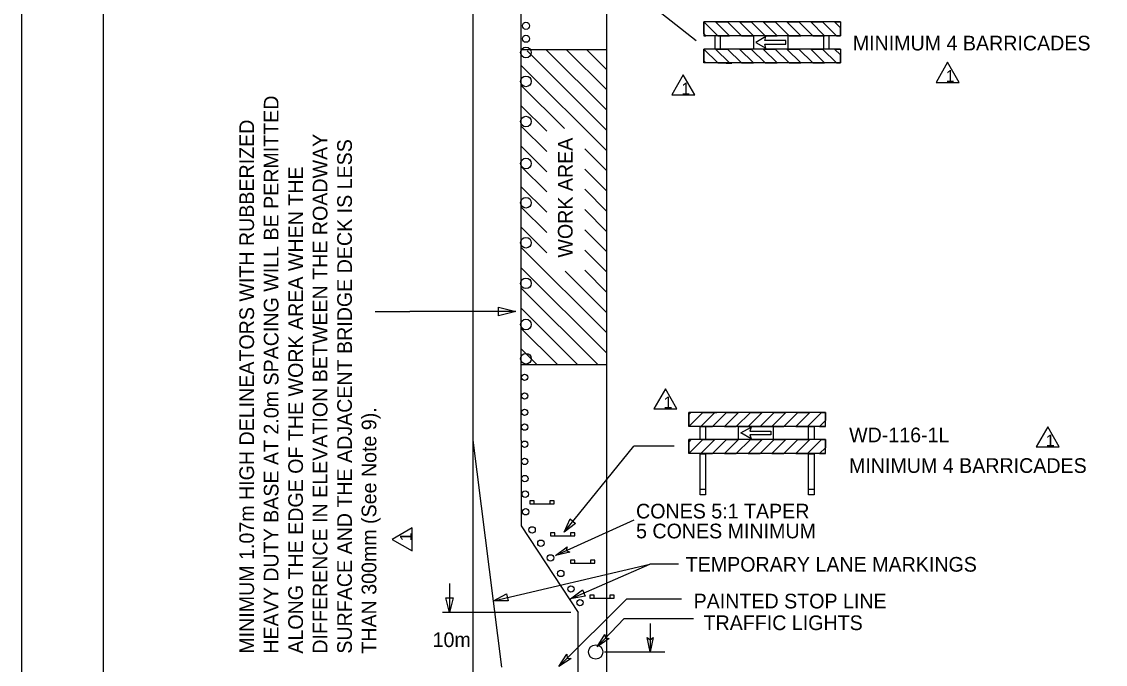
# Model space of a CAD drawing. Extents: x 1062 to 1288, y 239 to 518.
# Drawn here: x 1071.6 to 1204.5, y 374.1 to 453 of the extents above; entities that cross this region are included whole.
import ezdxf

# ---------------------------------------------------------------- set-up
doc = ezdxf.new("R2010")
doc.units = 0
for name, color, linetype in [('Level 10', 7, 'Continuous'), ('Level 44', 7, 'Continuous'), ('Level 5', 7, 'Continuous'), ('Level 60', 7, 'Continuous'), ('Level 7', 7, 'Continuous')]:
    doc.layers.add(name, color=color, linetype=linetype)

# ---------------------------------------------------------------- blocks, each defined once
blk = doc.blocks.new('TAH01')
at = {"layer": 'Level 5'}
blk.add_lwpolyline([(0, 0), (-3, -0.62), (-2.504, 0), (-3, 0.62)], close=True, dxfattribs=at)
blk = doc.blocks.new('LT1')
at = {"layer": 'Level 5'}
blk.add_blockref('TAH01', (0, 0), dxfattribs=at)

msp = doc.modelspace()

# ---------------------------------------------------------------- linework, layer by layer
at = {"layer": 'Level 10'}
for p, q in [((1143.33, 449.55), (1143.33, 505.33)), ((1126.93, 449.55), (1126.93, 459)), ((1126.93, 410.9), (1126.93, 449.55)), ((1143.33, 449.55), (1132.84, 449.55)), ((1143.33, 439.64), (1133.55, 449.41)), ((1143.33, 442.12), (1135.9, 449.55)), ((1143.33, 444.61), (1138.38, 449.55)), ((1143.33, 447.09), (1140.87, 449.55)), ((1143.33, 410.9), (1143.33, 449.55)), ((1143.33, 437.15), (1132.84, 447.63)), ((1138.13, 439.86), (1132.84, 445.15)), ((1135.96, 439.55), (1132.84, 442.67)), ((1135.96, 437.06), (1132.84, 440.18)), ((1135.96, 434.58), (1132.84, 437.7)), ((1143.33, 434.67), (1140.61, 437.39)), ((1135.96, 432.09), (1132.84, 435.21)), ((1143.33, 432.18), (1140.61, 434.9)), ((1135.96, 429.61), (1132.84, 432.73)), ((1143.33, 429.7), (1140.61, 432.42)), ((1135.96, 427.12), (1132.84, 430.24)), ((1143.33, 427.21), (1140.61, 429.93)), ((1135.96, 424.64), (1132.84, 427.76)), ((1143.33, 424.73), (1140.61, 427.45)), ((1143.33, 414.79), (1132.84, 425.27)), ((1143.33, 422.25), (1140.61, 424.96)), ((1143.33, 412.31), (1132.84, 422.79)), ((1143.33, 417.28), (1138.23, 422.37)), ((1143.33, 419.76), (1140.61, 422.48)), ((1142.24, 410.91), (1132.84, 420.3)), ((1139.73, 410.93), (1132.84, 417.82)), ((1137.22, 410.95), (1132.84, 415.33)), ((1134.79, 410.9), (1132.84, 412.85)), ((1126.93, 401.62), (1126.93, 411.52)), ((1143.33, 410.9), (1132.84, 410.9)), ((1143.33, 411.01), (1143.21, 410.9)), ((1143.33, 249.99), (1143.33, 410.9)), ((1130.44, 373.79), (1126.93, 401.62)), ((1126.93, 250.01), (1126.93, 401.62)), ((1132.84, 401.62), (1132.84, 391.12)), ((1132.84, 391.12), (1139.81, 380.51)), ((1137.57, 387.73), (1146.67, 391.86)), ((1129.41, 381.94), (1148.61, 386.42)), ((1138.89, 382.18), (1148.61, 386.42)), ((1152.12, 386.42), (1148.61, 386.42)), ((1124.04, 384.03), (1124.04, 380.51)), ((1137.44, 373.87), (1145.8, 382.16)), ((1145.8, 382.16), (1152.48, 382.16)), ((1138.93, 380.51), (1123.16, 380.51)), ((1139.81, 250.01), (1139.81, 380.51)), ((1142.15, 376.27), (1145.44, 379.74)), ((1145.44, 379.74), (1153.95, 379.74)), ((1148.63, 379.14), (1148.63, 375.65)), ((1143.04, 375.65), (1150.43, 375.65))]:
    msp.add_line(p, q, dxfattribs=at)
for points in [[(1131.22, 381.92), (1129.41, 381.94), (1131.02, 382.77)], [(1140.68, 382.48), (1138.89, 382.18), (1140.33, 383.29)], [(1124.48, 382.27), (1124.04, 380.51), (1123.6, 382.27)]]:
    msp.add_lwpolyline(points, close=True, dxfattribs=at)
for centre, radius in [((1133.41, 452.48), 0.434), ((1133.41, 450.89), 0.434), ((1133.41, 449.2), 0.652), ((1133.41, 445.66), 0.652), ((1133.41, 440.73), 0.652), ((1133.41, 435.59), 0.652), ((1133.41, 430.77), 0.652), ((1133.41, 425.86), 0.652), ((1133.41, 420.88), 0.652), ((1133.41, 415.83), 0.652), ((1133.41, 411.63), 0.652)]:
    msp.add_circle(centre, radius, dxfattribs=at)
at = {"layer": 'Level 44'}
msp.add_circle((1141.96, 375.65), 0.878, dxfattribs=at)
at = {"layer": 'Level 5'}
for p, q in [((1132.84, 401.62), (1132.84, 461.72)), ((1171.97, 452.98), (1155.22, 452.98)), ((1155.22, 452.98), (1155.22, 451.26)), ((1171.97, 452.98), (1171.97, 451.26)), ((1171.97, 451.26), (1155.22, 451.26)), ((1170.6, 451.26), (1170.26, 451.26)), ((1155.22, 449.63), (1155.22, 447.92)), ((1171.97, 449.63), (1155.22, 449.63)), ((1156.59, 449.67), (1156.59, 449.63)), ((1161.33, 449.65), (1165.56, 449.65)), ((1161.33, 449.65), (1165.56, 449.65)), ((1169.91, 449.67), (1169.91, 449.63)), ((1171.97, 449.63), (1171.97, 447.92)), ((1171.97, 447.92), (1155.22, 447.92)), ((1157.96, 447.9), (1158.65, 447.9)), ((1170.6, 447.92), (1170.26, 447.92)), ((1153.37, 405.07), (1170.13, 405.07)), ((1153.38, 403.33), (1153.38, 405.05)), ((1156.13, 405.05), (1156.82, 405.05)), ((1170.14, 403.33), (1170.14, 405.05)), ((1170.14, 403.33), (1153.38, 403.33)), ((1154.76, 403.3), (1154.76, 403.33)), ((1159.5, 403.31), (1163.72, 403.31)), ((1159.5, 403.31), (1163.72, 403.31)), ((1168.08, 403.3), (1168.08, 403.33)), ((1153.38, 399.98), (1153.38, 401.7)), ((1170.14, 401.7), (1153.38, 401.7)), ((1168.76, 401.7), (1168.42, 401.7)), ((1170.14, 399.98), (1170.14, 401.7)), ((1151.57, 400.89), (1146.64, 400.89)), ((1170.14, 399.98), (1153.38, 399.98)), ((1155.44, 395.6), (1154.76, 395.6)), ((1168.76, 395.6), (1168.08, 395.6)), ((1134.41, 394.19), (1133.88, 394.19)), ((1133.88, 394.19), (1133.88, 393.82)), ((1133.88, 393.82), (1136.86, 393.82)), ((1134.41, 393.82), (1134.41, 394.19)), ((1136.86, 394.19), (1136.34, 394.19)), ((1136.34, 394.19), (1136.34, 393.82)), ((1136.86, 393.82), (1136.86, 394.19)), ((1136.95, 390.26), (1136.42, 390.26)), ((1136.42, 390.26), (1136.42, 389.89)), ((1136.42, 389.89), (1139.4, 389.89)), ((1136.95, 389.89), (1136.95, 390.26)), ((1139.4, 390.26), (1138.88, 390.26)), ((1138.88, 390.26), (1138.88, 389.89)), ((1139.4, 389.89), (1139.4, 390.26)), ((1139.41, 386.91), (1138.89, 386.91)), ((1138.89, 386.91), (1138.89, 386.54)), ((1139.41, 386.54), (1139.41, 386.91)), ((1141.87, 386.91), (1141.34, 386.91)), ((1141.34, 386.91), (1141.34, 386.54)), ((1141.87, 386.54), (1141.87, 386.91)), ((1138.89, 386.54), (1141.87, 386.54)), ((1141.77, 382.62), (1141.24, 382.62)), ((1141.24, 382.62), (1141.24, 382.25)), ((1141.24, 382.25), (1144.22, 382.25)), ((1141.77, 382.25), (1141.77, 382.62)), ((1144.22, 382.62), (1143.69, 382.62)), ((1143.69, 382.62), (1143.69, 382.25)), ((1144.22, 382.25), (1144.22, 382.62))]:
    msp.add_line(p, q, dxfattribs=at)
for points in [[(1155.22, 452.98), (1156.93, 451.26), (1155.48, 451.26), (1155.22, 451.52), (1155.22, 452.98)], [(1158.13, 452.98), (1159.85, 451.26), (1158.39, 451.26), (1156.67, 452.98), (1158.13, 452.98)], [(1161.04, 452.98), (1162.76, 451.26), (1161.3, 451.26), (1159.59, 452.98), (1161.04, 452.98)], [(1163.96, 452.98), (1165.67, 451.26), (1164.22, 451.26), (1162.5, 452.98), (1163.96, 452.98)], [(1168.59, 451.26), (1167.13, 451.26), (1165.41, 452.98), (1166.87, 452.98), (1168.59, 451.26)], [(1171.5, 451.26), (1170.04, 451.26), (1168.33, 452.98), (1169.78, 452.98), (1171.5, 451.26)], [(1171.97, 452.25), (1171.24, 452.98), (1171.97, 452.98), (1171.97, 452.25)], [(1155.22, 449.63), (1156.93, 447.92), (1155.48, 447.92), (1155.22, 448.18), (1155.22, 449.63)], [(1158.13, 449.63), (1159.85, 447.92), (1158.39, 447.92), (1156.67, 449.63), (1158.13, 449.63)], [(1161.04, 449.63), (1162.76, 447.92), (1161.3, 447.92), (1159.59, 449.63), (1161.04, 449.63)], [(1163.96, 449.63), (1165.67, 447.92), (1164.22, 447.92), (1162.5, 449.63), (1163.96, 449.63)], [(1168.59, 447.92), (1167.13, 447.92), (1165.41, 449.63), (1166.87, 449.63), (1168.59, 447.92)], [(1171.5, 447.92), (1170.04, 447.92), (1168.33, 449.63), (1169.78, 449.63), (1171.5, 447.92)], [(1171.97, 448.9), (1171.24, 449.63), (1171.97, 449.63), (1171.97, 448.9)], [(1153.38, 403.33), (1155.1, 405.05), (1153.64, 405.05), (1153.38, 404.79), (1153.38, 403.33)], [(1156.3, 403.33), (1158.01, 405.05), (1156.56, 405.05), (1154.84, 403.33), (1156.3, 403.33)], [(1159.21, 403.33), (1160.93, 405.05), (1159.47, 405.05), (1157.75, 403.33), (1159.21, 403.33)], [(1162.12, 403.33), (1163.84, 405.05), (1162.38, 405.05), (1160.67, 403.33), (1162.12, 403.33)], [(1166.75, 405.05), (1165.3, 405.05), (1163.58, 403.33), (1165.04, 403.33), (1166.75, 405.05)], [(1169.67, 405.05), (1168.21, 405.05), (1166.49, 403.33), (1167.95, 403.33), (1169.67, 405.05)], [(1170.14, 404.06), (1169.41, 403.33), (1170.14, 403.33), (1170.14, 404.06)], [(1153.38, 399.98), (1155.1, 401.7), (1153.64, 401.7), (1153.38, 401.44), (1153.38, 399.98)], [(1156.3, 399.98), (1158.01, 401.7), (1156.56, 401.7), (1154.84, 399.98), (1156.3, 399.98)], [(1159.21, 399.98), (1160.93, 401.7), (1159.47, 401.7), (1157.75, 399.98), (1159.21, 399.98)], [(1162.12, 399.98), (1163.84, 401.7), (1162.38, 401.7), (1160.67, 399.98), (1162.12, 399.98)], [(1166.75, 401.7), (1165.3, 401.7), (1163.58, 399.98), (1165.04, 399.98), (1166.75, 401.7)], [(1169.67, 401.7), (1168.21, 401.7), (1166.49, 399.98), (1167.95, 399.98), (1169.67, 401.7)], [(1170.14, 400.71), (1169.41, 399.98), (1170.14, 399.98), (1170.14, 400.71)]]:
    msp.add_lwpolyline(points, dxfattribs=at)
for points in [[(1156.93, 451.26), (1158.39, 451.26), (1156.67, 452.98), (1155.22, 452.98)], [(1159.85, 451.26), (1161.3, 451.26), (1159.59, 452.98), (1158.13, 452.98)], [(1162.76, 451.26), (1164.22, 451.26), (1162.5, 452.98), (1161.04, 452.98)], [(1165.67, 451.26), (1167.13, 451.26), (1165.41, 452.98), (1163.96, 452.98)], [(1168.59, 451.26), (1170.04, 451.26), (1168.33, 452.98), (1166.87, 452.98)], [(1171.5, 451.26), (1171.97, 451.26), (1171.97, 452.25), (1171.24, 452.98), (1169.78, 452.98)], [(1155.22, 451.26), (1155.48, 451.26), (1155.22, 451.52)], [(1156.59, 449.67), (1157.28, 449.63), (1157.28, 451.26), (1156.59, 451.26)], [(1165.56, 449.65), (1165.56, 451.26), (1161.3, 451.26), (1161.3, 449.65)], [(1165.28, 450.22), (1165.28, 450.67), (1162.7, 450.67), (1162.84, 451.15), (1161.61, 450.44), (1162.84, 449.73), (1162.7, 450.22)], [(1165.28, 450.22), (1165.28, 450.67), (1162.7, 450.67), (1162.84, 451.15), (1161.61, 450.44), (1162.84, 449.73), (1162.7, 450.22)], [(1169.91, 449.67), (1170.6, 449.67), (1170.6, 451.26), (1169.91, 451.26)], [(1156.93, 447.92), (1158.39, 447.92), (1156.67, 449.63), (1155.22, 449.63)], [(1159.85, 447.92), (1161.3, 447.92), (1159.59, 449.63), (1158.13, 449.63)], [(1162.76, 447.92), (1164.22, 447.92), (1162.5, 449.63), (1161.04, 449.63)], [(1165.67, 447.92), (1167.13, 447.92), (1165.41, 449.63), (1163.96, 449.63)], [(1168.59, 447.92), (1170.04, 447.92), (1168.33, 449.63), (1166.87, 449.63)], [(1171.5, 447.92), (1171.97, 447.92), (1171.97, 448.9), (1171.24, 449.63), (1169.78, 449.63)], [(1155.48, 447.92), (1155.22, 447.92), (1155.22, 448.18)], [(1155.1, 405.05), (1156.56, 405.05), (1154.84, 403.33), (1153.38, 403.33)], [(1153.64, 405.05), (1153.38, 405.05), (1153.38, 404.79)], [(1158.01, 405.05), (1159.47, 405.05), (1157.75, 403.33), (1156.3, 403.33)], [(1160.93, 405.05), (1162.38, 405.05), (1160.67, 403.33), (1159.21, 403.33)], [(1163.84, 405.05), (1165.3, 405.05), (1163.58, 403.33), (1162.12, 403.33)], [(1166.75, 405.05), (1168.21, 405.05), (1166.49, 403.33), (1165.04, 403.33)], [(1169.67, 405.05), (1170.14, 405.05), (1170.14, 404.06), (1169.41, 403.33), (1167.95, 403.33)], [(1154.76, 403.3), (1155.44, 403.33), (1155.44, 401.7), (1154.76, 401.7)], [(1163.72, 403.31), (1163.72, 401.7), (1159.47, 401.7), (1159.47, 403.31)], [(1163.45, 402.75), (1163.45, 402.3), (1160.87, 402.3), (1161.01, 401.82), (1159.77, 402.53), (1161.01, 403.23), (1160.87, 402.75)], [(1168.08, 403.3), (1168.76, 403.3), (1168.76, 401.7), (1168.08, 401.7)], [(1153.38, 401.7), (1153.64, 401.7), (1153.38, 401.44)], [(1155.1, 401.7), (1156.56, 401.7), (1154.84, 399.98), (1153.38, 399.98)], [(1158.01, 401.7), (1159.47, 401.7), (1157.75, 399.98), (1156.3, 399.98)], [(1160.93, 401.7), (1162.38, 401.7), (1160.67, 399.98), (1159.21, 399.98)], [(1163.84, 401.7), (1165.3, 401.7), (1163.58, 399.98), (1162.12, 399.98)], [(1166.75, 401.7), (1168.21, 401.7), (1166.49, 399.98), (1165.04, 399.98)], [(1169.67, 401.7), (1170.14, 401.7), (1170.14, 400.71), (1169.41, 399.98), (1167.95, 399.98)], [(1154.76, 399.96), (1155.44, 399.96), (1155.44, 394.92), (1154.76, 394.92)], [(1168.08, 399.96), (1168.76, 399.96), (1168.76, 394.92), (1168.08, 394.92)]]:
    msp.add_lwpolyline(points, close=True, dxfattribs=at)
for centre in [(1133.25, 409.35), (1133.25, 407.06), (1133.25, 405.05), (1133.25, 403.24), (1133.25, 401.14), (1133.25, 399.03), (1133.27, 396.92), (1133.32, 395.01), (1133.38, 392.85), (1134.16, 390.63), (1135.24, 388.99), (1136.42, 387.19), (1137.68, 385.28), (1138.93, 383.37), (1140.03, 381.69)]:
    msp.add_circle(centre, 0.391, dxfattribs=at)
at = {"layer": 'Level 60'}
for p in [(1114.93, 417.41), (1132.15, 417.41)]:
    msp.add_line(p, (1119.17, 417.41), dxfattribs=at)
for points in [[(1287.56, 517.93), (1071.56, 517.93), (1071.56, 238.93), (1287.56, 238.93)], [(1268.44, 507.12), (1081.56, 507.12), (1081.56, 249.74), (1268.44, 249.74)], [(1185.12, 448), (1183.7, 445.53), (1186.54, 445.53)], [(1152.71, 446.47), (1151.29, 444), (1154.13, 444)], [(1130.03, 417.94), (1132.15, 417.41), (1130.03, 416.88)], [(1150.52, 407.94), (1149.1, 405.47), (1151.93, 405.47)], [(1197.4, 403.28), (1195.98, 400.81), (1198.82, 400.81)], [(1116.99, 389.46), (1119.46, 388.04), (1119.46, 390.88)]]:
    msp.add_lwpolyline(points, close=True, dxfattribs=at)
at = {"layer": 'Level 7'}
for p, q in [((1137.53, 463.96), (1154.29, 450.66)), ((1138.09, 390.36), (1146.64, 400.89))]:
    msp.add_line(p, q, dxfattribs=at)
msp.add_lwpolyline([(1139.5, 391.43), (1138.09, 390.36), (1138.83, 391.97)], close=True, dxfattribs=at)

# ---------------------------------------------------------------- block references
at = {"layer": 'Level 5'}
for p, xscale, yscale, rotation in [((1137.02, 387.48), 0.5856406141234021, 0.5856406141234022, -155.58392455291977), ((1142.15, 376.27), 0.5856406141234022, 0.5856406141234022, -133.52008430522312), ((1148.63, 375.65), 0.5856406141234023, 0.5856406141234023, -90), ((1137.44, 373.87), 0.5856406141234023, 0.5856406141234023, -135.25684626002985)]:
    msp.add_blockref('LT1', p, dxfattribs=dict(at, xscale=xscale, yscale=yscale, rotation=rotation))

# ---------------------------------------------------------------- texts
at = {"layer": 'Level 10'}
for s, p in [('MINIMUM 4 BARRICADES', (1173.49, 449.46)), ('WD-116-1L', (1173.04, 401.38)), ('MINIMUM 4 BARRICADES', (1173.03, 397.62)), ('CONES 5:1 TAPER', (1146.91, 392.03)), ('5 CONES MINIMUM', (1146.91, 389.59)), ('TEMPORARY LANE MARKINGS', (1153, 385.5)), ('PAINTED STOP LINE', (1153.97, 380.99)), ('TRAFFIC LIGHTS', (1155.19, 378.33)), ('10m', (1121.96, 376.25))]:
    msp.add_text(s, height=1.8, dxfattribs=at).set_placement(p)
for s, p in [('HEAVY DUTY BASE AT 2.0m SPACING WILL BE PERMITTED', (1103.06, 375.44)), ('MINIMUM 1.07m HIGH DELINEATORS WITH RUBBERIZED', (1100.06, 375.44)), ('DIFFERENCE IN ELEVATION BETWEEN THE ROADWAY', (1109.06, 375.44)), ('WORK AREA', (1139.13, 424.04)), ('SURFACE AND THE ADJACENT BRIDGE DECK IS LESS', (1112.06, 375.44)), ('ALONG THE EDGE OF THE WORK AREA WHEN THE', (1106.06, 375.44)), ('THAN 300mm (See Note 9).', (1115.06, 375.44))]:
    msp.add_text(s, height=1.8, rotation=90, dxfattribs=at).set_placement(p)
at = {"layer": 'Level 60'}
for rotation, p in [(360, (1184.89, 445.59)), (360, (1152.48, 444.05)), (360, (1150.29, 405.53)), (360, (1197.17, 400.87)), (90, (1119.4, 389.24))]:
    msp.add_text('1', height=1.45, rotation=rotation, dxfattribs=at).set_placement(p)

doc.saveas('drawing.dxf')
